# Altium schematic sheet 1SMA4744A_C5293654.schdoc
size 127 x 101 mm
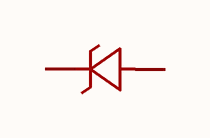
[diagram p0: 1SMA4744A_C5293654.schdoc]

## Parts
U?  1sma4744a_c5293654  [SMA_L4.3-W2.5-LS5.4-RD]  (value not drawn)

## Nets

Not connected (* = marked no-connect by the designer): U? 1(C) 2(A)

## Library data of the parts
U? = 1sma4744a_c5293654: 稳压值(标称值):15V;稳压值(范围):-;耗散功率(Pd):1W;; Manufacturer: CJ(江苏长电/长晶); AddInBom: yes; ModelId: d92a338144244ea8bab2c734703d07fa; ModelTransform: 204.724,110.236,0,0,0,0,0,0,0; Zener Voltage(Nom): 15V; Reverse Leakage Current (Ir): 100nA; Pd - Power Dissipation: 1W; Impedance(Zzt): 14Ω; Impedance(Zzk): 700Ω; Operating Junction Temperature Range: -55℃~+150℃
